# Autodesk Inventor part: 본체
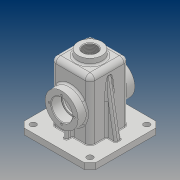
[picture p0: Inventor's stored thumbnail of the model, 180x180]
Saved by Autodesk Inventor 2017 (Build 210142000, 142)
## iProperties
Part Number: 본체
Material: 일반
Document SubType Name: Modeling
Designer: 20
Density: 1 g/cm^3
Appearance: 기본값
Mass: 293.223 g
Surface Area: 897.811 cm^2
Volume: 293.223 cm^3
Author: 20
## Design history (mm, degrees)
sketch "스케치1"
  geometry: L1 (-32.5, -32.5)-(32.5, -32.5); L2 (32.5, -32.5)-(32.5, 32.5); L3 (32.5, 32.5)-(-32.5, 32.5); L4 (-32.5, 32.5)-(-32.5, -32.5); L5 (-32.5, -32.5)-(32.5, 32.5); L6 (32.5, -32.5)-(-32.5, 32.5); 1 further point
  constraints: 12 end point, 2 midpoint, 2 parallel, 1 horizontal, 1 perpendicular
  dimensions: "d0" = 65 distance of L3.end L2.end; "d1" = 65 distance of L2.end L1.end
extrude "돌출1" new body sketch "스케치1" stored distance "d2" = 110; taper "d3" = 0 deg
fillet "모깎기1" dims "d4" = 8
feature "쉘1" dims "d5" = 5
sketch "스케치2"
  geometry: L1 (60, -60)-(-60, -60); L2 (-60, -60)-(-60, 60); L3 (-60, 60)-(60, 60); L4 (60, 60)-(60, -60); L5 (60, -60)-(-60, 60); L6 (-60, -60)-(60, 60); L7 (-27.5, -24.5)-(-27.5, 24.5) reference; L8 (24.5, -27.5)-(-24.5, -27.5) reference; L9 (27.5, 24.5)-(27.5, -24.5) reference; L10 (-24.5, 27.5)-(24.5, 27.5) reference; A1 r 3 centre (-24.5, -24.5) between (-27.5, -24.5) and (-24.5, -27.5) reference; A2 r 3 centre (24.5, -24.5) between (24.5, -27.5) and (27.5, -24.5) reference; A3 r 3 centre (24.5, 24.5) between (27.5, 24.5) and (24.5, 27.5) reference; A4 r 3 centre (-24.5, 24.5) between (-24.5, 27.5) and (-27.5, 24.5) reference; 1 further point
  constraints: 12 end point, 2 midpoint, 2 parallel, 1 horizontal, 1 perpendicular
  dimensions: "d6" = 120 distance of L2.end L3.end; "d7" = 120 distance of L1.end L2.end
extrude "돌출2" join sketch "스케치2" distance "d8" = 10; taper "d9" = 0 deg
sketch "스케치3"
  geometry: L1 (-60, -45)-(60, -45) reference; L2 (48, -45)-(36.539, 20); L3 (60, -55)-(60, -45) reference; 1 further point
  constraints: 2 end point, 1 point on line
  dimensions: "d10" = 12 distance from line of L3 L2.start; "d11" = 10 deg angle of L3 L2; "d12" = 65 vertical distance of L2.start L2.end
feature "리브1" sketch "스케치3" dims "d13" = 1, "d14" = 10, "d15" = 0, "d16" = 0, "d17" = 1, "d18" = 1
node "작업 평면1"
sketch "스케치5"
  geometry: C1 r 27.5 at (24.5, -47); 1 further point
  constraints: 1 centre point, 1 coincident
  dimensions: "d23" = 55 diameter of C1
extrude "돌출4" join sketch "스케치5" stored distance "d24" = 15; taper "d25" = 0 deg
hole "구멍1" diameter "d28" = 30; stored, may be unused: countersink angle "d32" = 90 deg, drill point angle "d34" = 118 deg; dims "d26" = 10, "d27" = 10, "d29" = 6, "d30" = 35, "d31" = 17, "d33" = 8
sketch "스케치6"
  geometry: 2 further points
  constraints: 1 vertical alignment
  dimensions: "d35" = 21 distance of point (0, 0) point (0, 21)
hole "구멍2" sketch "스케치6" at (0, 21) diameter "d36" = 3.242; stored, may be unused: countersink angle "d40" = 90 deg, drill point angle "d42" = 118 deg; dims "d37" = 8, "d38" = 35, "d39" = 17, "d41" = 10
node "작업 평면2"
sketch "스케치7"
  geometry: C1 r 20 at (0, 0); 1 further point
  constraints: 1 centre point, 1 coincident
  dimensions: "d47" = 40 diameter of C1
extrude "돌출5" join sketch "스케치7" stored distance "d48" = 15; taper "d49" = 5 deg
hole "구멍3" diameter "d52" = 22.835; stored, may be unused: countersink angle "d56" = 90 deg, drill point angle "d58" = 118 deg; dims "d50" = 10, "d51" = 10, "d53" = 50, "d54" = 35, "d55" = 17, "d57" = 59.3
sketch "스케치8"
  geometry: L1 (0, 39.5)-(0, -39.5); L2 (24.5, 27.5)-(-24.5, 27.5) reference; L3 (-24.5, -27.5)-(24.5, -27.5) reference; L4 (-3, 39.5)-(-3, 27.5); L5 (-3, -27.5)-(-3, -39.5); L6 (3, -39.5)-(3, -27.5); L7 (3, 27.5)-(3, 39.5); A1 r 3 centre (0, 39.5) between (3, 39.5) and (-3, 39.5); A2 r 3 centre (0, -39.5) between (-3, -39.5) and (3, -39.5); 3 further points
  constraints: 12 end point, 8 tangent, 5 point on circle, 4 parallel, 4 point on line, 2 centre point, 1 coincident, 1 midpoint, 1 vertical, 1 vertical alignment
  dimensions: "d59" = 6 diameter of A2; "d60" = 12 distance from line of L2 L1.start; "d61" = 15 distance from line of point (0, -42.5) L3 (derived)
extrude "돌출6" join sketch "스케치8" stored distance "d62" = 15; taper "d63" = 0 deg; dims "d6" = 120, "d7" = 120
chamfer "모따기1" distance "d64" = 10; stored, may be unused: second distance "d65" = 2, angle "d66" = 45 deg
sketch "스케치9"
  geometry: L1 (-60, 50)-(-60, -50) reference; L2 (-50, -60)-(50, -60) reference; C1 r 5 at (-47.5, -47.5); C2 r 5 at (-47.5, 47.5); C3 r 5 at (47.5, -47.5); C4 r 5 at (47.5, 47.5); 1 further point
  constraints: 4 centre point, 1 horizontal, 1 vertical, 6 other
  dimensions: "d67" = 10 diameter of C1; "d68" = 12.5 distance from line of L1 C1.centre; "d69" = 12.5 distance from line of L2 C1.centre; "d72" = 95 distance of C1.centre C2.centre; "d75" = 95 distance of C1.centre C3.centre
extrude "돌출7" cut sketch "스케치9" stored distance "d78" = 10; taper "d79" = 0 deg
fillet "모깎기2" dims "d80" = 3
fillet "모깎기3" dims "d81" = 3
fillet "모깎기4" dims "d82" = 1
fillet "모깎기5" dims "d83" = 0.3
node "작업 평면3"
sketch "스케치10"
  geometry: L1 (44.5, -18)-(4.5, -18) reference; L2 (57, 0)-(57, 91) reference; 2 further points
  constraints: 1 other
  dimensions: "d85" = 26 distance from line of point (24.5, 8) L1; "d86" = 32.5 distance from line of L2 point (24.5, 8)
feature "엠보싱1" sketch "스케치10" dims "d0" = 65, "d1" = 65, "d6" = 120, "d7" = 120, "d87" = 0.5, "d88" = 0
chamfer "모따기2" distance "d89" = 1; stored, may be unused: second distance "d90" = 2, angle "d91" = 45 deg
fillet "모깎기6" dims "d92" = 3
node "솔리드1"
mirror "미러1"
pattern_circular "원형 패턴1" dims angle "d44" = 360 deg
mirror "미러2"
other parameters: "d22" = 15, "d84" = 30.5
